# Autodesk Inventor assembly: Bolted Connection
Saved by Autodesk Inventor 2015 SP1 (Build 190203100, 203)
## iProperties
Created: 2011-06
Part Number: Bolted Connection
Document SubType Name: Assembly
Designer: Guilherme Augusto Franco de Souza
ClientObjectVersion: 1
Author: Guilherme Augusto Franco de Souza
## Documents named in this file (1)
- E:\Visitor Experience Project\WSI2015 - Visitor Experience Project\#46- Sheet Metal Technology\01- 3D Models\Outodoor Heater\2- Assemblies\Outdoor Burner\Design Accelerator\Bolted Connection1.iam
